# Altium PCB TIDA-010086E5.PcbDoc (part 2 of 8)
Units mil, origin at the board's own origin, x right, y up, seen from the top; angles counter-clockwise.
Board outline 6400 x 6200 mil, 6 copper layers (Top Layer, Power, AGND, Signal, PGND, Bottom Layer), stack 70.536 mil thick; 717 components, 376 nets, 2259 pads, 2183 vias.
Unrouted connection lines stored in the file: 1424.
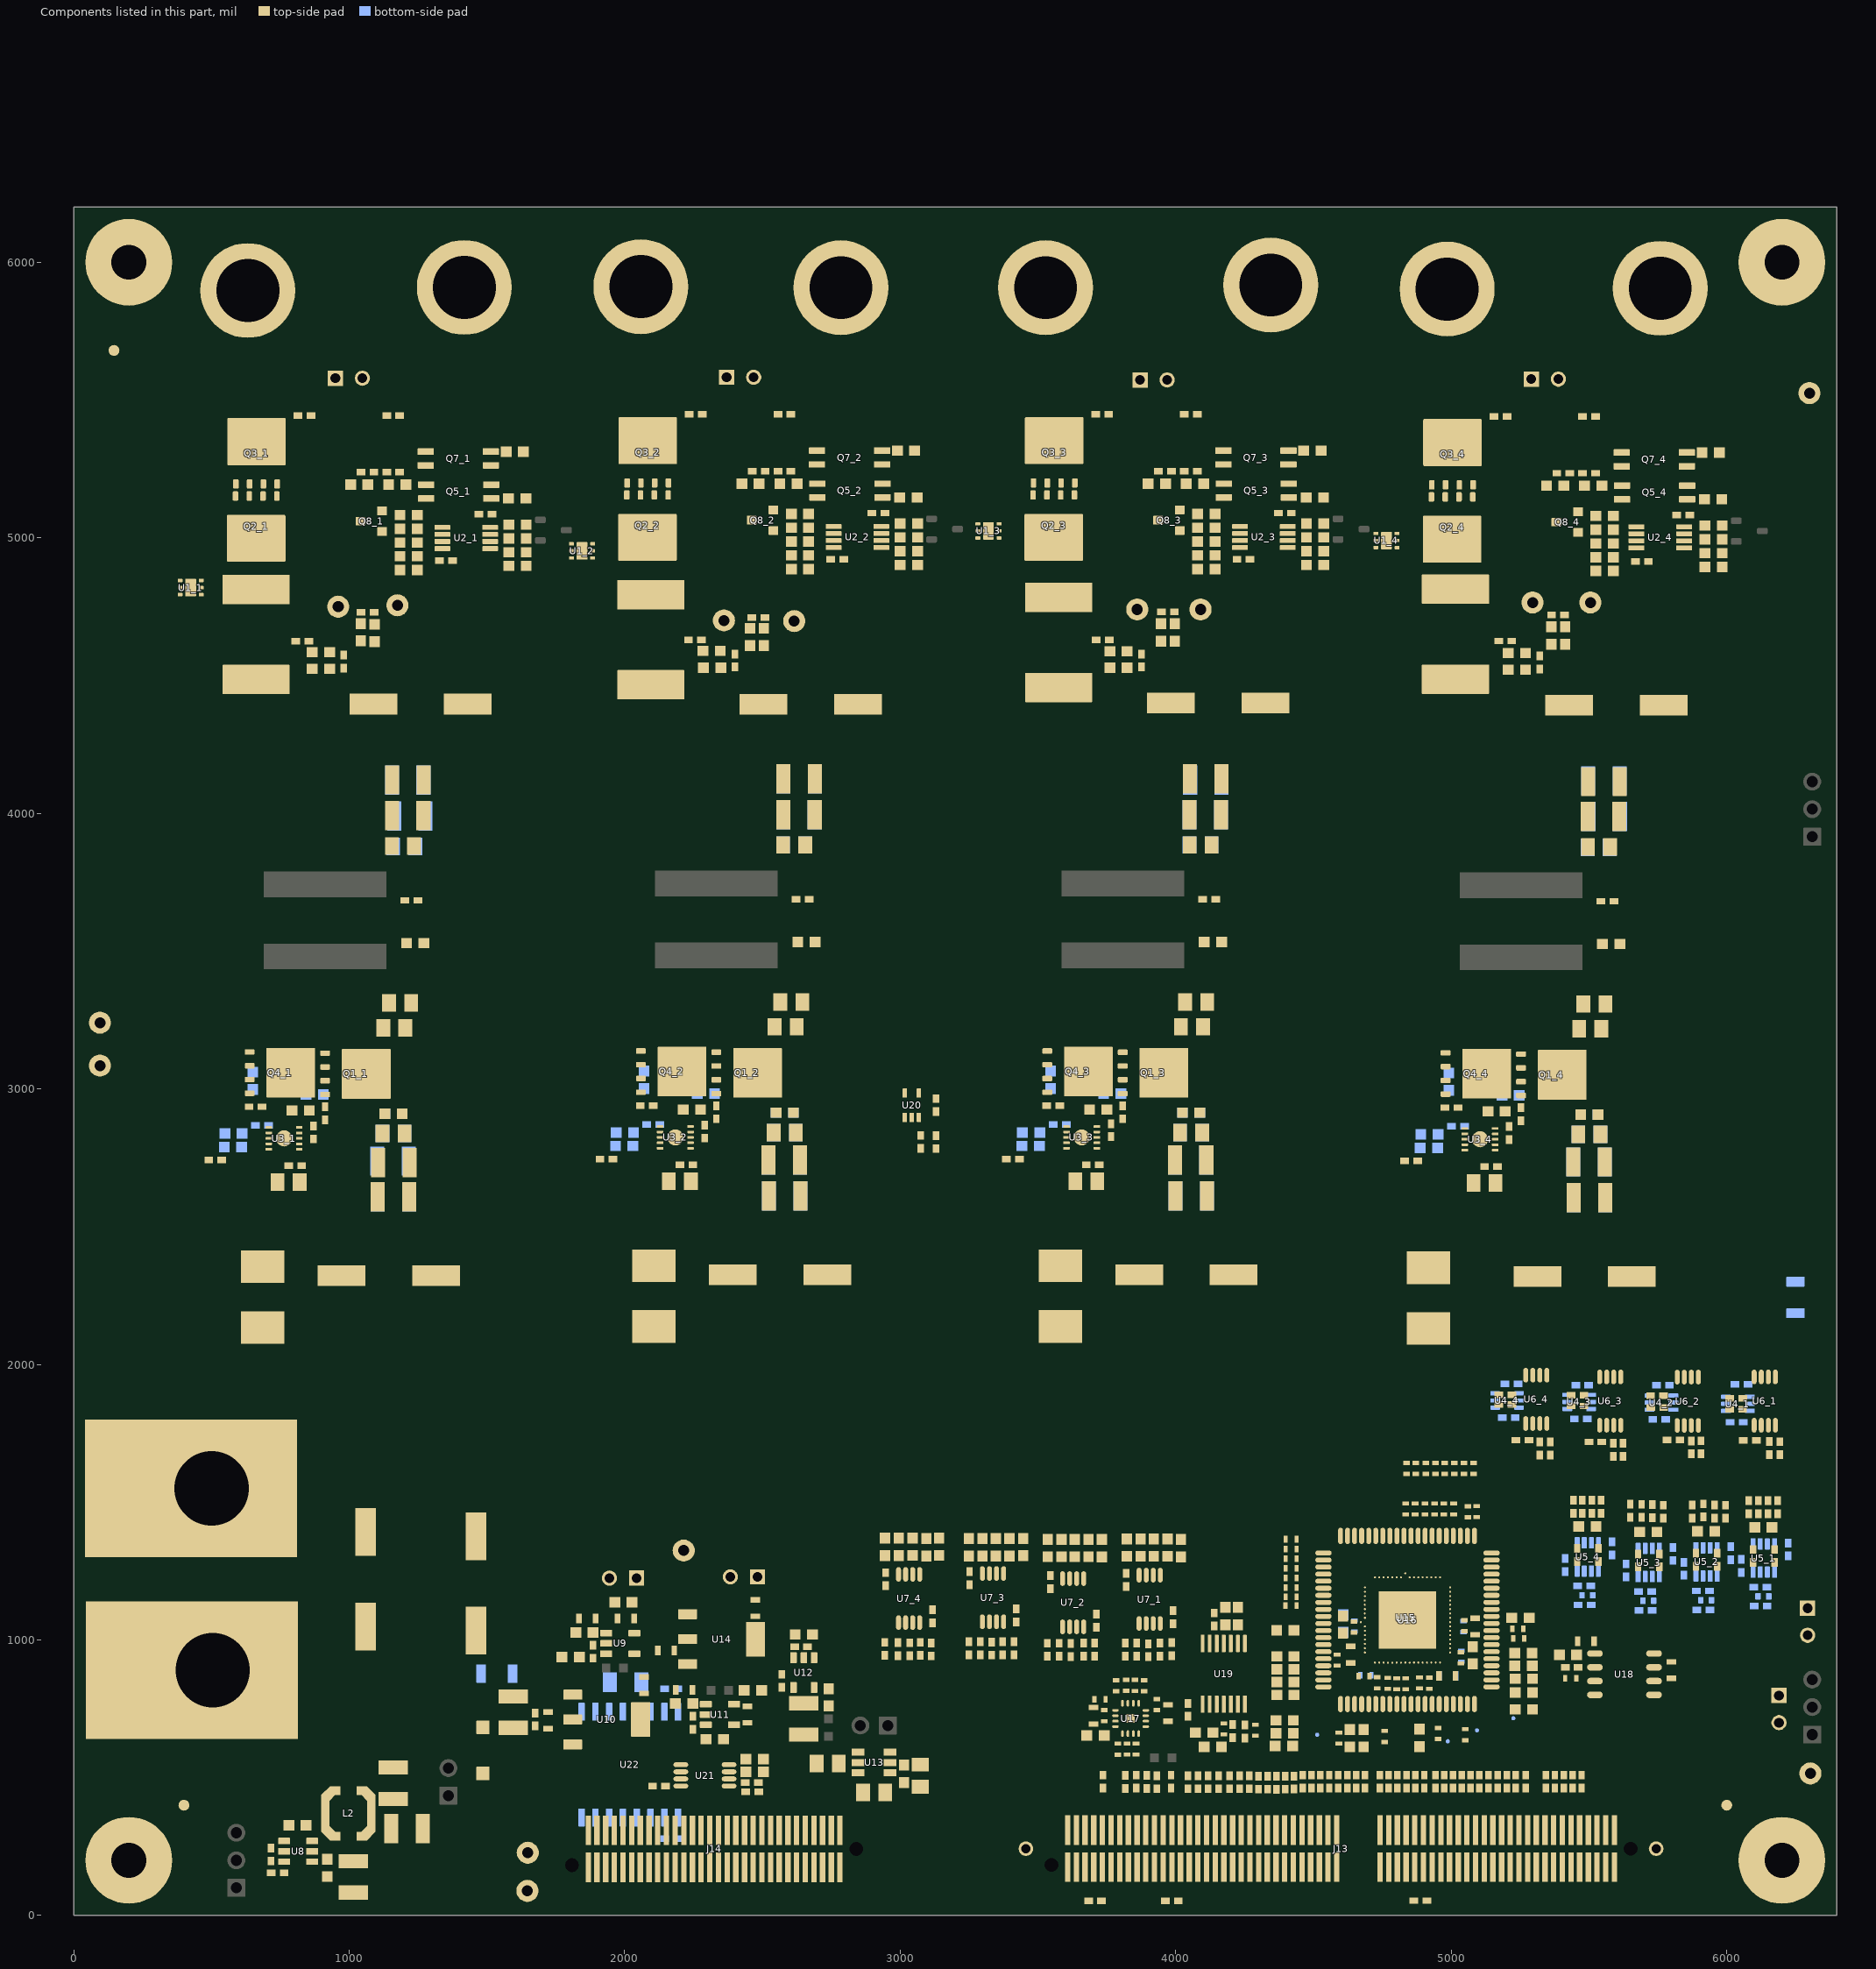
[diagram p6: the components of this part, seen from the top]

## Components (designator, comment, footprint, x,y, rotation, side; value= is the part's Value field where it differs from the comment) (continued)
R27_1 "CRCW04020000Z0ED" 0402 1065.85,5237.76 r0 top value=0 (schematic designator R27)
R27_2 "CRCW04020000Z0ED" 0402 2485.97,5241.34 r0 top value=0 (schematic designator R27)
R27_3 "CRCW04020000Z0ED" 0402 3960.97,5241.34 r0 top value=0 (schematic designator R27)
R27_4 "CRCW04020000Z0ED" 0402 5406.75,5234.5 r0 top value=0 (schematic designator R27)
R28_1 "CRCW060349K9FKEA" 0603 1610.85,4947.76 r0 top value=49.9k (schematic designator R28)
R28_2 "CRCW060349K9FKEA" 0603 3030.97,4951.34 r0 top value=49.9k (schematic designator R28)
R28_3 "CRCW060349K9FKEA" 0603 4505.97,4951.34 r0 top value=49.9k (schematic designator R28)
R28_4 "CRCW060349K9FKEA" 0603 5951.75,4944.5 r0 top value=49.9k (schematic designator R28)
R29_1 "CRCW06031K00JNEA" 0603 1600.85,5312.76 r0 top value=1.0k (schematic designator R29)
R29_2 "CRCW06031K00JNEA" 0603 3020.97,5316.34 r0 top value=1.0k (schematic designator R29)
R29_3 "CRCW06031K00JNEA" 0603 4495.97,5316.34 r0 top value=1.0k (schematic designator R29)
R29_4 "CRCW06031K00JNEA" 0603 5941.75,5309.5 r0 top value=1.0k (schematic designator R29)
R30_1 "CRCW06034K99FKEAC" 0603 1610.85,4997.76 r180 top value=4.99k (schematic designator R30)
R30_2 "CRCW06034K99FKEAC" 0603 3030.97,5001.34 r180 top value=4.99k (schematic designator R30)
R30_3 "CRCW06034K99FKEAC" 0603 4505.97,5001.34 r180 top value=4.99k (schematic designator R30)
R30_4 "CRCW06034K99FKEAC" 0603 5951.75,4994.5 r180 top value=4.99k (schematic designator R30)
R31_1 "CRCW04020000Z0ED" 0402 1159.52,5237.76 r0 top value=0 (schematic designator R31)
R31_2 "CRCW04020000Z0ED" 0402 2579.64,5241.34 r0 top value=0 (schematic designator R31)
R31_3 "CRCW04020000Z0ED" 0402 4054.64,5241.34 r0 top value=0 (schematic designator R31)
R31_4 "CRCW04020000Z0ED" 0402 5500.42,5234.5 r0 top value=0 (schematic designator R31)
R32_1 "CRCW04020000Z0ED" 0402 6033.68,1837.57 r180 top value=0 (schematic designator R32)
R32_2 "CRCW04020000Z0ED" 0402 5747.37,1842.75 r180 top value=0 (schematic designator R32)
R32_3 "CRCW04020000Z0ED" 0402 5458.04,1848.89 r180 top value=0 (schematic designator R32)
R32_4 "CRCW04020000Z0ED" 0402 5196.24,1853.83 r180 top value=0 (schematic designator R32)
R33_1 "CRCW04020000Z0ED" 0402 6172.82,1304.5 r270 top value=0 (schematic designator R33)
R33_2 "CRCW04020000Z0ED" 0402 5964.79,1290.69 r270 top value=0 (schematic designator R33)
R33_3 "CRCW04020000Z0ED" 0402 5754.87,1288.41 r270 top value=0 (schematic designator R33)
R33_4 "CRCW04020000Z0ED" 0402 5533.78,1308.4 r270 top value=0 (schematic designator R33)
R34_1 "CRCW0402499RFKED" 0402 6149.41,1481.6 r270 top value=499 (schematic designator R34)
R34_2 "CRCW0402499RFKED" 0402 5955.6,1465.3 r270 top value=499 (schematic designator R34)
R34_3 "CRCW0402499RFKED" 0402 5729.35,1467.44 r270 top value=499 (schematic designator R34)
R34_4 "CRCW0402499RFKED" 0402 5510.48,1483.4 r270 top value=499 (schematic designator R34)
R35_1 "CRCW04020000Z0ED" 0402 6053.15,1927.64 r0 bottom value=0 (schematic designator R35)
R35_2 "CRCW04020000Z0ED" 0402 5768.23,1923.89 r0 bottom value=0 (schematic designator R35)
R35_3 "CRCW04020000Z0ED" 0402 5475.29,1925.07 r0 bottom value=0 (schematic designator R35)
R35_4 "CRCW04020000Z0ED" 0402 5218.14,1929.83 r0 bottom value=0 (schematic designator R35)
R36_1 "RT0402BRD0720KL" 0402 6121.63,1191.75 r180 bottom value=20.0k (schematic designator R36)
R36_2 "RT0402BRD0720KL" 0402 5913.61,1177.94 r180 bottom value=20.0k (schematic designator R36)
R36_3 "RT0402BRD0720KL" 0402 5703.69,1175.65 r180 bottom value=20.0k (schematic designator R36)
R36_4 "RT0402BRD0720KL" 0402 5482.6,1195.65 r180 bottom value=20.0k (schematic designator R36)
R37_1 "CRCW0402499RFKED" 0402 6114.41,1481.6 r270 top value=499 (schematic designator R37)
R37_2 "CRCW0402499RFKED" 0402 5915,1470 r270 top value=499 (schematic designator R37)
R37_3 "CRCW0402499RFKED" 0402 5690.85,1468.43 r270 top value=499 (schematic designator R37)
R37_4 "CRCW0402499RFKED" 0402 5475.48,1483.4 r270 top value=499 (schematic designator R37)
R38_1 "RT0402BRD07100RL" FP-RT0402BRD07100RL_0402-MFG 6132.82,1158.12 r180 bottom value=100 (schematic designator R38)
R38_2 "RT0402BRD07100RL" FP-RT0402BRD07100RL_0402-MFG 5924.79,1144.32 r180 bottom value=100 (schematic designator R38)
R38_3 "RT0402BRD07100RL" FP-RT0402BRD07100RL_0402-MFG 5714.87,1142.03 r180 bottom value=100 (schematic designator R38)
R38_4 "RT0402BRD07100RL" FP-RT0402BRD07100RL_0402-MFG 5493.78,1162.02 r180 bottom value=100 (schematic designator R38)
R39_1 "CRCW04020000Z0ED" 0402 6033.95,1876.79 r180 top value=0 (schematic designator R39)
R39_2 "CRCW04020000Z0ED" 0402 5747.04,1885.9 r180 top value=0 (schematic designator R39)
R39_3 "CRCW04020000Z0ED" 0402 5458.04,1888.42 r180 top value=0 (schematic designator R39)
R39_4 "CRCW04020000Z0ED" 0402 5196.24,1888.83 r180 top value=0 (schematic designator R39)
R40_1 "CRCW04020000Z0ED" 0402 6122.82,1123.12 r180 bottom value=0 (schematic designator R40)
R40_2 "CRCW04020000Z0ED" 0402 5914.79,1109.32 r180 bottom value=0 (schematic designator R40)
R40_3 "CRCW04020000Z0ED" 0402 5704.87,1107.03 r180 bottom value=0 (schematic designator R40)
R40_4 "CRCW04020000Z0ED" 0402 5483.78,1127.02 r180 bottom value=0 (schematic designator R40)
R41_1 "CRCW04020000Z0ED" 0402 6096.04,1304.5 r270 top value=0 (schematic designator R41)
R41_2 "CRCW04020000Z0ED" 0402 5888.02,1290.69 r270 top value=0 (schematic designator R41)
R41_3 "CRCW04020000Z0ED" 0402 5678.1,1288.41 r270 top value=0 (schematic designator R41)
R41_4 "CRCW04020000Z0ED" 0402 5457.01,1308.4 r270 top value=0 (schematic designator R41)
R42_1 "CRCW060310K0FKEA" 0603 1239.52,3529.08 r180 top value=10.0k (schematic designator R42)
R42_2 "CRCW060310K0FKEA" 0603 2659.64,3532.67 r180 top value=10.0k (schematic designator R42)
R42_3 "CRCW060310K0FKEA" 0603 4134.64,3532.67 r180 top value=10.0k (schematic designator R42)
R42_4 "CRCW060310K0FKEA" 0603 5580.42,3525.83 r180 top value=10.0k (schematic designator R42)
R43 "CRCW04020000Z0ED" 0402S 5080.95,1622.46 r270 top value=0
R44_1 "PCF0402-12-10K0BT1" 0402 3985.69,966.05 r270 top value=10.0k (schematic designator R44)
R44_2 "PCF0402-12-10K0BT1" 0402 3705,965 r270 top value=10.0k (schematic designator R44)
R44_3 "PCF0402-12-10K0BT1" 0402 3412.54,969.36 r270 top value=10.0k (schematic designator R44)
R44_4 "PCF0402-12-10K0BT1" 0402 3112.68,965.47 r270 top value=10.0k (schematic designator R44)
R45_1 "CRCW060320K0FKEA" 0603 4018.88,1332.82 r270 top value=20.0k (schematic designator R45)
R45_2 "CRCW060320K0FKEA" 0603 3731.74,1332.8 r270 top value=20.0k (schematic designator R45)
R45_3 "CRCW060320K0FKEA" 0603 3446.51,1336.9 r270 top value=20.0k (schematic designator R45)
R45_4 "CRCW060320K0FKEA" 0603 3141.03,1338.15 r270 top value=20.0k (schematic designator R45)
R46_1 "CRCW040240K2FKED" 0402 3942.54,964.91 r90 top value=40.2k (schematic designator R46)
R46_2 "CRCW040240K2FKED" 0402 3665.85,965 r90 top value=40.2k (schematic designator R46)
R46_3 "CRCW040240K2FKED" 0402 3371.54,969.36 r90 top value=40.2k (schematic designator R46)
R46_4 "CRCW040240K2FKED" 0402 3072.4,967.26 r90 top value=40.2k (schematic designator R46)
R47_1 "CRCW060349K9FKEA" 0603 3970.3,1335.12 r90 top value=49.9k (schematic designator R47)
R47_2 "CRCW060349K9FKEA" 0603 3682.95,1333.57 r90 top value=49.9k (schematic designator R47)
R47_3 "CRCW060349K9FKEA" 0603 3396.51,1336.34 r90 top value=49.9k (schematic designator R47)
R47_4 "CRCW060349K9FKEA" 0603 3094.57,1336.34 r90 top value=49.9k (schematic designator R47)
R48_1 "CRCW040240K2FKED" 0402 3900.3,962.37 r90 top value=40.2k (schematic designator R48)
R48_2 "CRCW040240K2FKED" 0402 3618.88,962.92 r90 top value=40.2k (schematic designator R48)
R48_3 "CRCW040240K2FKED" 0402 3331.51,968.58 r90 top value=40.2k (schematic designator R48)
R48_4 "CRCW040240K2FKED" 0402 3034.36,965.68 r90 top value=40.2k (schematic designator R48)
R49_1 "CRCW04020000Z0ED" 0402 6154.37,1696.52 r270 top value=0 (schematic designator R49)
R49_2 "CRCW04020000Z0ED" 0402 5871.37,1698.64 r270 top value=0 (schematic designator R49)
R49_3 "CRCW04020000Z0ED" 0402 5587.6,1690.07 r270 top value=0 (schematic designator R49)
R49_4 "CRCW04020000Z0ED" 0402 5321.48,1694.89 r270 top value=0 (schematic designator R49)
R50_1 "CRCW060349K9FKEA" 0603 3920.3,1335.12 r90 top value=49.9k (schematic designator R50)
R50_2 "CRCW060349K9FKEA" 0603 3632.95,1333.57 r90 top value=49.9k (schematic designator R50)
R50_3 "CRCW060349K9FKEA" 0603 3346.51,1336.34 r90 top value=49.9k (schematic designator R50)
R50_4 "CRCW060349K9FKEA" 0603 3044.99,1338.15 r90 top value=49.9k (schematic designator R50)
R51_1 "PCF0402-12-10K0BT1" 0402 3816.32,964.64 r270 top value=10.0k (schematic designator R51)
R51_2 "PCF0402-12-10K0BT1" 0402 3533.43,964.2 r270 top value=10.0k (schematic designator R51)
R51_3 "PCF0402-12-10K0BT1" 0402 3248.72,969.4 r270 top value=10.0k (schematic designator R51)
R51_4 "PCF0402-12-10K0BT1" 0402 2943.3,967.46 r270 top value=10.0k (schematic designator R51)
R52_1 "CRCW060320K0FKEA" 0603 3872.5,1335.12 r270 top value=20.0k (schematic designator R52)
R52_2 "CRCW060320K0FKEA" 0603 3585.15,1333.57 r270 top value=20.0k (schematic designator R52)
R52_3 "CRCW060320K0FKEA" 0603 3298.72,1336.34 r270 top value=20.0k (schematic designator R52)
R52_4 "CRCW060320K0FKEA" 0603 2994.39,1337.58 r270 top value=20.0k (schematic designator R52)
R53 "CRCW0402255KFKED" 0402 740,155 r0 top value=255k
R54 "CRCW040222K1FKED" 0402 715.84,221.1 r270 top value=22.1k
R55 "CRCW12060000Z0EAC" FP-CRCW12060000Z0EAC_1206-MFG 6249.33,2242.79 r90 bottom value=0
R56 "CRCW12060000Z0EAC" FP-CRCW12060000Z0EAC_1206-MFG 1536.07,877.68 r0 bottom value=0
R57 "CRCW06031K00JNEA" 0603 1995.31,1136.75 r0 top value=1.0k
R58 "CRCW06031K00JNEA" 0603 2465.39,817.01 r0 top value=1.0k
R59 "CRCW060349K9FKEA" 0603 1853.82,1027.18 r180 top value=49.9k
R60 "CRCW060349K9FKEA" 0603 2215.39,769.22 r180 top value=49.9k
R61 "CRCW060310K0FKEA" 0603 1803.82,937.37 r0 top value=10.0k
R62 "CRCW060310K0FKEA" 0603 2326.89,639.22 r180 top value=10.0k
R63 "CRCW06031K00JNEA" 0603 3013.77,513.77 r90 top value=1.0k
R64 "CRCW06031K00JNEA" 0603 2740,791.42 r90 top value=1.0k
R65 "CRCW04020000Z0ED" 0402S 4801.97,840.58 r270 top value=0
R66 "CRCW04020000Z0ED" 0402S 4768.67,842.04 r270 top value=0
R67 "CRCW04020000Z0ED" 0402S 4884.57,843.8 r270 top value=0
R68 "CRCW04020000Z0ED" 0402S 4730.96,844.49 r270 top value=0
R69 "CRCW060310K0FKEA" 0603 4392.66,614.55 r0 top value=10.0k
R70 "CRCW060310K0FKEA" 0603 5263.2,808.55 r0 top value=10.0k
R71 "CRCW04020000Z0ED" 0402S 4591.96,643.38 r270 top value=0
R72 "CRCW04020000Z0ED" 0402S 5092.75,1466 r270 top value=0
R73 "CRCW04020000Z0ED" 0402S 4919.78,842.68 r270 top value=0
R74 "CRCW04020000Z0ED" 0402S 5245,1005 r180 top value=0
R75 "CRCW04020000Z0ED" 0402S 4758.37,649.4 r270 top value=0
R76 "CRCW04020000Z0ED" 0402S 5241.76,1040.85 r180 top value=0
R77 "CRCW04020000Z0ED" 0402S 4951.84,660.34 r270 top value=0
R78 "CRCW04020000Z0ED" 0402S 4585.69,926.36 r270 top value=0
R79 "CRCW04020000Z0ED" 0402S 5051.1,655.86 r270 top value=0
R80 "CRCW060310K0FKEA" 0603 5263.2,748.07 r180 top value=10.0k
R81 "CRCW060310K0FKEA" 0603 4397.92,893.58 r0 top value=10.0k
R82 "CRCW060310K0FKEA" 0603 4395.14,661.05 r0 top value=10.0k
R83 "CRCW060310K0FKEA" 0603 4395.14,708.14 r0 top value=10.0k
R84 "CRCW060310K0FKEA" 0603 5263.2,859.01 r180 top value=10.0k
R85 "CRCW060310K0FKEA" 0603 5262.01,906.01 r180 top value=10.0k
R86 "CRCW060310K0FKEA" 0603 5261.89,952.01 r180 top value=10.0k
R87 "CRCW04020000Z0ED" 0402S 4418.38,1330.45 r0 top value=0
R88 "CRCW04020000Z0ED" 0402S 4418.38,1365.45 r0 top value=0
R89 "CRCW04020000Z0ED" 0402S 4418.38,1260.45 r0 top value=0
R90 "CRCW060310K0FKEA" 0603 4397.92,800.57 r0 top value=10.0k
R91 "CRCW060310K0FKEA" 0603 4681.96,643.38 r270 top value=10.0k
R92 "CRCW060310K0FKEA" 0603 4631.96,643.38 r90 top value=10.0k
R93 "CRCW060310K0FKEA" 0603 4397.92,847.14 r180 top value=10.0k
R94 "CRCW04020000Z0ED" 0402S 4418.38,1295.45 r0 top value=0
R95 "CRCW04020000Z0ED" 0402S 4418.38,1190.45 r0 top value=0
R96 "CRCW04020000Z0ED" 0402S 4418.38,1225.45 r0 top value=0
R97 "CRCW04020000Z0ED" 0402S 4418.35,1124.62 r0 top value=0
R98 "CRCW060310K0FKEA" 0603 4397.92,940.15 r180 top value=10.0k
R99 "CRCW04020000Z0ED" 0402S 4418.38,1156.78 r0 top value=0
R100 "CRCW04020000Z0ED" 0402S 3852.41,834.83 r270 top value=0
R101 "CRCW04020000Z0ED" 0402S 3820,835 r270 top value=0
R102 "CRCW04020000Z0ED" 0402S 3783.87,833.66 r270 top value=0
R103 "CRCW04020000Z0ED" 0402S 3725,785 r0 top value=0
R104 "CRCW04020000Z0ED" 0402S 3885.06,833.66 r90 top value=0
R105 "CRCW04020000Z0ED" 0402S 3823.61,603.97 r270 top value=0
R106 "CRCW04020000Z0ED" 0402S 3790.35,603.38 r270 top value=0
R107 "CRCW04020000Z0ED" 0402S 3855.8,604.14 r270 top value=0
R108 "CRCW060310K0FKEA" 0603 3708.5,653.22 r180 top value=10.0k
R109 "CRCW04020000Z0ED" 0402S 5433.64,860.5 r180 top value=0
R110 "CRCW060310K0FKEA" 0603 4102.74,663.27 r0 top value=10.0k
R111 "CRCW0402499RFKED" 0402 4043.58,746.13 r90 top value=499
R112 "ERJ-2BQFR22X" 0402 5437.26,900.5 r0 top value=0.22
R113 "CRCW060315K8FKEA" 0603 4134.23,611.84 r180 top value=15.8k
R114 "CRCW060310K0FKEA" 0603 4180,1086.5 r90 top value=10.0k
R115 "CRCW0402499RFKED" 0402 4251,667.27 r270 top value=499
R116 "CRCW060310K0FKEA" 0603 4225.41,1086.5 r90 top value=10.0k
R117 "CRCW04020000Z0ED" 0402S 4288.86,672.16 r270 top value=0
R118 "CRCW0402100RFKED" 0402 5234.07,485.5 r270 top value=100
R119 "CRCW0402100RFKED" 0402 5169.07,485.5 r270 top value=100
R120 "CRCW0402100RFKED" 0402 5102.07,485.5 r270 top value=100
R121 "CRCW0402100RFKED" 0402 5006.07,485.5 r270 top value=100
R122 "ERA-2AEB102X" 0402 3073.99,2807.11 r90 top value=1.00k
R123 "CRCW04020000Z0ED" 0402 5473,485.5 r270 top value=0
R124 "CRCW04020000Z0ED" 0402 5408.07,485.5 r90 top value=0
R125 "ERA-2AEB102X" 0402 3983,485.5 r270 top value=1.00k
R126 "CRCW04020000Z0ED" 0402 5376.07,485.5 r90 top value=0
R127 "CRCW04020000Z0ED" 0402 5343.07,485.5 r90 top value=0
R128 "CRCW04020000Z0ED" 0402 5270.07,485.5 r90 top value=0
R129 "CRCW04020000Z0ED" 0402 4974.07,485.5 r90 top value=0
R130 "CRCW040222R0JNED" 0402 4838,485.5 r270 top value=22
R131 "CRCW04020000Z0ED" 0402 4942.07,485.5 r90 top value=0
R132 "CRCW040222R0JNED" 0402 4804.07,485.5 r270 top value=22
R133 "CRCW04020000Z0ED" 0402 4902,485.5 r90 top value=0
R134 "CRCW040222R0JNED" 0402 4772.07,485.5 r270 top value=22
R135 "CRCW040222R0JNED" 0402 4870,485.5 r90 top value=22
R136 "CRCW040222R0JNED" 0402 4740.07,485.5 r270 top value=22
R137 "CRCW040222R0JNED" 0402 4687,485.5 r90 top value=22
R138 "CRCW04020000Z0ED" 0402 4590,485.5 r90 top value=0
R139 "CRCW04020000Z0ED" 0402 4557,485.5 r90 top value=0
R140 "CRCW040222R0JNED" 0402 4525,485.5 r90 top value=22
R141 "CRCW040222R0JNED" 0402 4429.15,482.17 r270 top value=22
R142 "CRCW040222R0JNED" 0402 4623,485.5 r90 top value=22
R143 "CRCW0402100RFKED" 0402 2462.5,449.18 r0 top value=100
R144 "CRCW040222R0JNED" 0402 4397,481.88 r270 top value=22
R145 "CRCW040222R0JNED" 0402 4493,485.5 r90 top value=22
R146 "CRCW040222R0JNED" 0402 4365,481.25 r270 top value=22
R147 "CRCW040222R0JNED" 0402 4461,485.5 r90 top value=22
R148 "CRCW040222R0JNED" 0402 4333.3,481.88 r270 top value=22
R149 "CRCW040222R0JNED" 0402 4655,485.5 r90 top value=22
R150 "CRCW040222R0JNED" 0402 4299.66,481.88 r270 top value=22
R151 "CRCW040222R0JNED" 0402 4267.2,483.38 r270 top value=22
R152 "CRCW040222R0JNED" 0402 4232.3,483.38 r270 top value=22
R153 "CRCW040222R0JNED" 0402 4043.58,483.38 r90 top value=22
R154 "CRCW040222R0JNED" 0402 4194.93,483.38 r270 top value=22
R155 "CRCW040222R0JNED" 0402 4155.93,483.38 r90 top value=22
R156 "CRCW06034K99FKEAC" 0603 2471.5,567.18 r180 top value=4.99k
R157 "CRCW060349K9FKEA" 0603 2471.5,521.18 r0 top value=49.9k
R158 "CRCW040222R0JNED" 0402 4117.05,483.38 r270 top value=22
R159 "CRCW040222R0JNED" 0402 4081.27,483.38 r270 top value=22
R160 "CRCW040222R0JNED" 0402 3931.43,483.38 r270 top value=22
R161 "CRCW040222R0JNED" 0402 3895,484.3 r270 top value=22
R162 "CRCW040222R0JNED" 0402 3857,485.5 r270 top value=22
R163 "CRCW040222R0JNED" 0402 3816.27,484.3 r270 top value=22
R164 "ERJ-8ENF59R0V" 1206 2003.59,846.27 r0 bottom value=59.0
R165 "CRCW04020000Z0ED" 0402S 5045.53,1622.46 r270 top value=0
R166 "CRCW04020000Z0ED" 0402S 5060,1465 r270 top value=0
R167 "CRCW04020000Z0ED" 0402S 5011.6,1622.46 r270 top value=0
R168 "CRCW04020000Z0ED" 0402S 5008.7,1475 r270 top value=0
R169 "CRCW04020000Z0ED" 0402S 4975.53,1622.46 r270 top value=0
R170 "CRCW04020000Z0ED" 0402S 4972.63,1475 r270 top value=0
R171 "CRCW04020000Z0ED" 0402S 4942.37,1622.46 r270 top value=0
R172 "CRCW04020000Z0ED" 0402S 4939.47,1475 r270 top value=0
R173 "CRCW04020000Z0ED" 0402S 4907.37,1622.46 r270 top value=0
R174 "CRCW04020000Z0ED" 0402S 4904.47,1475 r270 top value=0
R175 "CRCW04020000Z0ED" 0402S 4871.56,1622.46 r270 top value=0
R176 "CRCW04020000Z0ED" 0402S 4868.66,1475 r270 top value=0
R177 "CRCW04020000Z0ED" 0402S 4837.02,1622.46 r270 top value=0
R178 "CRCW04020000Z0ED" 0402S 4834.12,1475 r270 top value=0
R179 "CRCW04020000Z0ED" 0402S 4834.68,840.58 r270 top value=0
SH-J1 "60900213421" Wurth_60900213421 1187.27,648.32 r180 top
SH-J2 "60900213421" Wurth_60900213421 590,251.54 r270 top
SH-J3 "60900213421" Wurth_60900213421 2895.52,675.23 r0 top
T1 "CXS70-14-C" Panduit_CXS70-14-C 500.19,1550 r0 top
T2 "CXS70-14-C" Panduit_CXS70-14-C 504.28,890 r0 top
TP1_1 "5000" Keystone5000 1175,4755 r90 top (schematic designator TP1)
TP1_2 "5000" Keystone5000 2614.97,4697.68 r90 top (schematic designator TP1)
TP1_3 "5000" Keystone5000 4090,4740 r90 top (schematic designator TP1)
TP1_4 "5000" Keystone5000 5505,4765 r90 top (schematic designator TP1)
TP2_1 "5001" Keystone5001 960,4750 r90 top (schematic designator TP2)
TP2_2 "5001" Keystone5001 2360,4700 r90 top (schematic designator TP2)
TP2_3 "5001" Keystone5001 3860,4740 r90 top (schematic designator TP2)
TP2_4 "5001" Keystone5001 5295,4765 r90 top (schematic designator TP2)
TP3 "5001" Keystone5001 95.14,3240 r180 top
TP4 "5001" Keystone5001 6300,5525 r180 top
TP5 "5001" Keystone5001 95.14,3084.28 r180 top
TP6 "5001" Keystone5001 2213.97,1324.52 r180 top
TP7 "TP_SM_1MM" TP_SM_1MM 5093.44,671.82 r90 bottom
TP8 "TP_SM_1MM" TP_SM_1MM 4513.2,655.86 r90 bottom
TP9 "TP_SM_1MM" TP_SM_1MM 4987.31,632.19 r90 bottom
TP10 "TP_SM_1MM" TP_SM_1MM 5225.43,715.5 r90 bottom
TP11 "5001" Keystone5001 6303.42,515.46 r180 top
TP12 "5001" Keystone5001 1647.95,227.63 r270 top
TP13 "5001" Keystone5001 1646.57,89.2 r180 top
U1_1 "TVS0500DRVR" DRV0006A 424.52,4819.36 r0 top (schematic designator U1)
U1_2 "TVS0500DRVR" DRV0006A 1845,4952.72 r0 top (schematic designator U1)
U1_3 "TVS0500DRVR" DRV0006A 3320,5025 r0 top (schematic designator U1)
U1_4 "TVS0500DRVR" DRV0006A 4765,4990 r0 top (schematic designator U1)
U2_1 "LM393BIDGKR" DGK0008A-MFG 1424.64,4999.25 r0 top (schematic designator U2)
U2_2 "LM393BIDGKR" DGK0008A-MFG 2844.76,5002.83 r0 top (schematic designator U2)
U2_3 "LM393BIDGKR" DGK0008A-MFG 4319.76,5002.83 r0 top (schematic designator U2)
U2_4 "LM393BIDGKR" DGK0008A-MFG 5758.65,5001.88 r0 top (schematic designator U2)
U3_1 "UCC27284DRCR" DRC0010J-MFG 763.43,2820.24 r180 top (schematic designator U3)
U3_2 "UCC27284DRCR" DRC0010J-MFG 2183.54,2823.82 r180 top (schematic designator U3)
U3_3 "UCC27284DRCR" DRC0010J-MFG 3658.54,2823.82 r180 top (schematic designator U3)
U3_4 "UCC27284DRCR" DRC0010J-MFG 5104.32,2816.98 r180 top (schematic designator U3)
U4_1 "INA500B" DCK0006A-MFG 6040.31,1856.62 r0 bottom (schematic designator U4)
U4_2 "INA500B" DCK0006A-MFG 5762.95,1861 r0 bottom (schematic designator U4)
U4_3 "INA500B" DCK0006A-MFG 5464.42,1863.89 r0 bottom (schematic designator U4)
U4_4 "INA500B" DCK0006A-MFG 5202.62,1868.83 r0 bottom (schematic designator U4)
U5_1 "INA630" DDF0008A-MFG 6134.43,1296.94 r270 bottom (schematic designator U5)
U5_2 "INA630" DDF0008A-MFG 5926.4,1283.13 r270 bottom (schematic designator U5)
U5_3 "INA630" DDF0008A-MFG 5716.48,1280.85 r270 bottom (schematic designator U5)
U5_4 "INA630" DDF0008A-MFG 5495.4,1300.84 r270 bottom (schematic designator U5)
U6_1 "INA826AIDGK" DGK0008A_N 6137.84,1866.8 r270 top (schematic designator U6)
U6_2 "INA826AIDGK" DGK0008A_N 5858.28,1866.18 r270 top (schematic designator U6)
U6_3 "INA826AIDGK" DGK0008A_N 5576.73,1866.71 r270 top (schematic designator U6)
U6_4 "INA826AIDGK" DGK0008A_N 5308.68,1873.01 r270 top (schematic designator U6)
U7_1 "TLV9152IDGKR" DGK0008A_N 3905.3,1147.29 r90 top (schematic designator U7)
U7_2 "TLV9152IDGKR" DGK0008A_N 3627.46,1134.97 r90 top (schematic designator U7)
U7_3 "TLV9152IDGKR" DGK0008A_N 3336.51,1153.5 r90 top (schematic designator U7)
U7_4 "TLV9152IDGKR" DGK0008A_N 3032.19,1150.31 r90 top (schematic designator U7)
U8 "LMR54410DBVR" DBV0006A-MFG 814.52,232.6 r0 top
U9 "TPS7A2018PDBVR" DBV0005A-MFG 1983.82,987.37 r0 top
U10 "TLV1117LV30DCYR" DCY0004A_N 1934.45,711.08 r0 top
U11 "TPS7A2033PDBVR" DBV0005A-MFG 2345.39,729.22 r0 top
U12 "TPS73633DBVR" DBV0005A_N 2650,881.42 r270 top
U13 "PM-CHP-LM2664M6-6" DBV0006A_M 2905,555 r0 top
U14 "TLV1117LV30DCYR" DCY0004A_N 2351.53,1002.44 r0 top
U15 "ADS9324RSK" RSK0064B-MFG 4841.04,1072.35 r270 top
U16 "ADS8686SIPZA" PZA0080A_N 4841.04,1072.35 r270 top
U17 "DAC60504BRTET" RTE0016D 3836.01,714.88 r270 top
U18 "REF5040AIDR" D0008A_N 5628.64,875.5 r180 top
U19 "LM324BIPWR" PW0014A-MFG 4174.23,876.84 r90 top
U20 "TMP235DCK" DCK0005A_N 3041.86,2940.47 r90 top
U21 "TLV9152IDGKR" DGK0008A_N 2291.1,508.39 r180 top
U22 "ISO1050DWR" DW0016B_HV 2018.51,547.34 r90 bottom
ZZ1 "This Assembly Note is for PCB labels only" AssemblyNoteLabel 0,6600 r0 top
ZZ2 "These assemblies are ESD sensitive, ESD precautions shall be observed." AssemblyNote 0,6500 r0 top
ZZ3 "These assemblies must be clean and free from flux and all contaminants. Use of no clean flux is not acceptable." AssemblyNote 0,6400 r0 top
ZZ4 "These assemblies must comply with workmanship standards IPC-A-610 Class 2, unless otherwise specified." AssemblyNote 0,6300 r0 top

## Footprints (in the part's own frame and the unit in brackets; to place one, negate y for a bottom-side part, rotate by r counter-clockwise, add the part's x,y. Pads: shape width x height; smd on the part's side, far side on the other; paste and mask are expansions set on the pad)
0402 [mm] "0402 from SM-752 data"
  rect 0.8x0.6 smd: 1(-0.6,0) 2(0.6,0)
  silkscreen extent -1.22,-0.52 1.22,0.52, body extent -0.55,-0.3 0.55,0.3, height 0.6
0402S [mil] "Based on C0402S footprint from PADS legacy"
  rect 15x24 smd: 1(-20,0) 2(20,0)
  body extent -22,-12 22,12, height 24
0603 [mm] "0603 from SM-752 data"
  rect 1x0.95 smd: 1(-0.8,0) 2(0.8,0)
  silkscreen extent -1.52,-0.69 1.52,0.69, body extent -0.87,-0.47 0.87,0.47, height 1
0603S [mil]
  rect 20x35 smd: 1(-30,0) 2(30,0)
  body extent -34,-19 34,19, height 39
0805_HV [mil] "0805 with 30mil clearance between pads"
  rect 50x63 smd: 1(-40,0) 2(40,0)
  silkscreen extent -74,-40 74,40, body extent -43,-29 43,29, height 57
1206 [mm] "1206 from SM-752 data"
  rect 1.3x1.85 smd: 1(-1.45,0) 2(1.45,0)
  silkscreen extent -2.4,-1.21 2.4,1.21, body extent -1.7,-0.9 1.7,0.9, height 1.35
1210 [mm] "1210 from SM-752 data"
  rect 1.3x2.7 smd: 1(-1.45,0) 2(1.45,0)
  silkscreen extent -2.32,-1.57 2.32,1.57, body extent -1.7,-1.35 1.7,1.35, height 1.35
1210_270 [mm] "1210"
  rect 1.3x2.7 smd: 1(-1.45,0) 2(1.45,0)
  silkscreen extent -2.32,-1.57 2.32,1.57, body extent -1.7,-1.35 1.7,1.35, height 2.7
1806_HighSpeed [mm] "Wurth recommended land pattern"
  rrect8% 1.25x1.2 smd: 1(-2.125,0) 2(2.125,0)
  silkscreen extent -1.5,-1 1.5,1, body extent -2.25,-0.8 2.25,0.8, height 1.61
6125FA [mm] "Cooper Bussman 6125FA Brick Fuses, recommended land pattern OC-2531 Rev. I 3/07"
  rect 3x4 smd: 1(-2.8,0) 2(2.8,0)
  silkscreen extent -4.57,-2.27 4.57,2.27, body extent -3.17,-1.42 3.17,1.41, height 2.84
AssemblyNote [mil] "Assembly Note"
AssemblyNoteLabel [mil] "Assembly Note for PCB Labels"
CAPSMT_62_F12 [mm] "F12, SMD, 2-Leads, Body 10.5x10.5mm, Height 12.7mm"
  rect 4.4x1.9 smd: 1(-4.35,0) 2(4.35,0)
  silkscreen extent -5.25,-5.25 5.25,5.25, body extent -5.25,-5.25 5.25,5.25, height 12.71
CE_Mark_5mm [mil] "Minimum text height for CE Mark"
  silkscreen extent -138,-98 138,98
controlCARD-120HSEC [mm] "Pads are not numbered according to Samtec datasheet."
  rect 0.5x2.724 smd: 1(-23.357,-1.678) 2(-23.357,1.722) 3(-22.557,-1.678) 4(-22.557,1.722) 5(-21.757,-1.678) 6(-21.757,1.722) 7(-20.957,-1.678) 8(-20.957,1.722) 9(-20.157,-1.678) 10(-20.157,1.722) 11(-19.357,-1.678) 12(-19.357,1.722) 13(-18.557,-1.678) 14(-18.557,1.722) 15(-17.757,-1.678) 16(-17.757,1.722) 17(-16.957,-1.678) 18(-16.957,1.722) 19(-16.157,-1.678) 20(-16.157,1.722) 21(-15.357,-1.678) 22(-15.357,1.722) 23(-14.557,-1.678) 24(-14.557,1.722) 25(-13.757,-1.678) 26(-13.757,1.722) 27(-12.957,-1.678) 28(-12.957,1.722) 29(-12.157,-1.678) 30(-12.157,1.722) 31(-11.357,-1.678) 32(-11.357,1.722) 33(-10.557,-1.678) 34(-10.557,1.722) 35(-9.757,-1.678) 36(-9.757,1.722) 37(-8.957,-1.678) 38(-8.957,1.722) 39(-8.157,-1.678) 40(-8.157,1.722) 41(-7.357,-1.678) 42(-7.357,1.722) 43(-6.557,-1.678) 44(-6.557,1.722) 45(-5.757,-1.678) 46(-5.757,1.722) 47(-4.957,-1.678) 48(-4.957,1.722) 49(-4.157,-1.678) 50(-4.157,1.722) 51(-3.357,-1.678) 52(-3.357,1.722) 53(-2.557,-1.678) 54(-2.557,1.722) 55(-1.757,-1.678) 56(-1.757,1.722) 57(2.243,-1.678) 58(2.243,1.722) 59(3.043,-1.678) 60(3.043,1.722) 61(3.843,-1.678) 62(3.843,1.722) 63(4.643,-1.678) 64(4.643,1.722) 65(5.443,-1.678) 66(5.443,1.722) 67(6.243,-1.678) 68(6.243,1.722) 69(7.043,-1.678) 70(7.043,1.722) 71(7.843,-1.678) 72(7.843,1.722) 73(8.643,-1.678) 74(8.643,1.722) 75(9.443,-1.678) 76(9.443,1.722) 77(10.243,-1.678) 78(10.243,1.722) 79(11.043,-1.678) 80(11.043,1.722) 81(11.843,-1.678) 82(11.843,1.722) 83(12.643,-1.678) 84(12.643,1.722) 85(13.443,-1.678) 86(13.443,1.722) 87(14.243,-1.678) 88(14.243,1.722) 89(15.043,-1.678) 90(15.043,1.722) 91(15.843,-1.678) 92(15.843,1.722) 93(16.643,-1.678) 94(16.643,1.722) 95(17.443,-1.678) 96(17.443,1.722) 97(18.243,-1.678) 98(18.243,1.722) 99(19.043,-1.678) 100(19.043,1.722) 101(19.843,-1.678) 102(19.843,1.722) 103(20.643,-1.678) 104(20.643,1.722) 105(21.443,-1.678) 106(21.443,1.722) 107(22.243,-1.678) 108(22.243,1.722) 109(23.043,-1.678) 110(23.043,1.722) 111(23.843,-1.678) 112(23.843,1.722) 113(24.643,-1.678) 114(24.643,1.722) 115(25.443,-1.678) 116(25.443,1.722) 117(26.243,-1.678) 118(26.243,1.722) 119(27.043,-1.678) 120(27.043,1.722)
  round 0.025 hole 1.27 unplated mask+0.876: 181(-24.857,0.022) 182(28.543,1.522)
  round 1.348 hole 0.84: 185(-27.207,0.022) 186(30.893,0.022)
  silkscreen extent -32.11,-3.86 35.8,3.9, body extent -31.75,-3.48 35.3,3.52, height 12.35
controlCARD-180HSEC-60pinAddon [mm] "Pads are not numbered according to datasheet."
  round 0.025 hole 1.27 unplated mask+0.876: 61(-13.1,0) 62(13.1,1.5)
  rect 0.5x2.724 smd: 121(-11.6,-1.7) 122(-11.6,1.7) 123(-10.8,-1.7) 124(-10.8,1.7) 125(-10,-1.7) 126(-10,1.7) 127(-9.2,-1.7) 128(-9.2,1.7) 129(-8.4,-1.7) 130(-8.4,1.7) 131(-7.6,-1.7) 132(-7.6,1.7) 133(-6.8,-1.7) 134(-6.8,1.7) 135(-6,-1.7) 136(-6,1.7) 137(-5.2,-1.7) 138(-5.2,1.7) 139(-4.4,-1.7) 140(-4.4,1.7) 141(-3.6,-1.7) 142(-3.6,1.7) 143(-2.8,-1.7) 144(-2.8,1.7) 145(-2,-1.7) 146(-2,1.7) 147(-1.2,-1.7) 148(-1.2,1.7) 149(-0.4,-1.7) 150(-0.4,1.7) 151(0.4,-1.7) 152(0.4,1.7) 153(1.2,-1.7) 154(1.2,1.7) 155(2,-1.7) 156(2,1.7) 157(2.8,-1.7) 158(2.8,1.7) 159(3.6,-1.7) 160(3.6,1.7) 161(4.4,-1.7) 162(4.4,1.7) 163(5.2,-1.7) 164(5.2,1.7) 165(6,-1.7) 166(6,1.7) 167(6.8,-1.7) 168(6.8,1.7) 169(7.6,-1.7) 170(7.6,1.7) 171(8.4,-1.7) 172(8.4,1.7) 173(9.2,-1.7) 174(9.2,1.7) 175(10,-1.7) 176(10,1.7) 177(10.8,-1.7) 178(10.8,1.7) 179(11.6,-1.7) 180(11.6,1.7)
  silkscreen extent -14.68,-3.88 14.68,3.88, body extent -14.3,-3.5 14.3,3.5, height 7.95
D0008A_N [mm] "SOIC, 8-Leads, Body 4.9x3.9mm, Pitch 1.27mm, IPC Medium Density"
  oval 1.45x0.6 smd: 1(-2.725,1.905) 2(-2.725,0.635) 3(-2.725,-0.635) 4(-2.725,-1.905) 5(2.725,-1.905) 6(2.725,-0.635) 7(2.725,0.635) 8(2.725,1.905)
  silkscreen extent -3.3,-2.5 0.9,2.5, body extent -3,-2.45 3,2.45, height 1.63
DBV0005A-MFG [mm]
  rrect17% 1.1x0.6 smd paste+0 mask+0: 1(-1.3,0.95) 2(-1.3,0) 3(-1.3,-0.95) 4(1.3,-0.95) 5(1.3,0.95)
  silkscreen extent -2.57,-1.53 0.87,1.53, body extent -1.95,-1.78 1.95,1.78, height 0.25
DBV0005A_N [mm] "SOT23, 5-Leads, Body 2.9x1.6mm, Pitch 0.95mm, Lead Span 2.8mm, IPC Medium Density"
  rrect17% 1x0.6 smd: 1(-1.375,0.95) 2(-1.375,0) 3(-1.375,-0.95) 4(1.375,-0.95) 5(1.375,0.95)
  silkscreen extent -1.63,-1.55 0.38,1.55, body extent -1.42,-1.46 1.42,1.46, height 1.09
DBV0006A-MFG [mm]
  rrect17% 1.1x0.6 smd paste+0 mask+0: 1(-1.3,0.95) 2(-1.3,0) 3(-1.3,-0.95) 4(1.3,-0.95) 5(1.3,0) 6(1.3,0.95)
  silkscreen extent -2.52,-1.53 0.35,1.53, body extent -1.95,-1.78 1.95,1.78, height 0.25
DBV0006A_M [mm] "SOT23, 6-Leads, Body 2.9x1.6mm, Pitch 0.95mm, Lead Span 2.8mm, IPC Low Density"
  rrect15% 1.2x0.65 smd: 1(-1.475,0.95) 2(-1.475,0) 3(-1.475,-0.95) 4(1.475,-0.95) 5(1.475,0) 6(1.475,0.95)
  silkscreen extent -1.83,-1.55 0.38,1.55, body extent -1.42,-1.46 1.42,1.46, height 1.12
DCK0005A_N [mm] "SOT353, 5-Leads, Body 2x1.3mm, Pitch 0.65mm, Lead Span 2.1mm, IPC Medium Density"
  rrect25% 0.85x0.4 smd: 1(-1.125,0.65) 2(-1.125,0) 3(-1.125,-0.65) 4(1.125,-0.65) 5(1.125,0.65)
  silkscreen extent -1.48,-1.02 0.55,1.1, body extent -1.14,-1 1.14,1, height 0.95
DCK0006A-MFG [mm]
  rrect25% 0.9x0.4 smd paste-1000 mask+0: 1(-1.1,0.65) 2(-1.1,0) 3(-1.1,-0.65) 4(1.1,-0.65) 5(1.1,0) 6(1.1,0.65)
  silkscreen extent -2.22,-1.07 0.27,1.07, body extent -1.1,-1 1.1,1, height 1.1
DCY0004A_N [mm] "SOT223/SC73, 4-Leads, Body 6.5x3.5mm, Pitch 2.3mm, Lead Span 7mm, IPC Medium Density"
  rrect11% 1.75x0.9 smd: 1(-3.125,2.3) 2(-3.125,0) 3(-3.125,-2.3)
  rrect6% 1.75x3.2 smd: 4(3.125,0)
  silkscreen extent -3.02,-3.35 1.4,3.47, body extent -3.48,-3.25 3.48,3.25, height 1.68
DDF0008A-MFG [mm]
  rrect22% 1.05x0.45 smd paste+0 mask+0: 1(-1.3,0.975) 2(-1.3,0.325) 3(-1.3,-0.325) 4(-1.3,-0.975) 5(1.3,-0.975) 6(1.3,-0.325) 7(1.3,0.325) 8(1.3,0.975)
  silkscreen extent -2.5,-1.48 0.4,1.48, body extent -1.41,-1.45 1.41,1.45, height 1.1
DFH0004A-MFG [mm]
  rrect17% 1.5x0.6 smd paste+0 mask+0: 1(-3,0.635) 2(-3,-0.635) 3(3,-0.635) 4(3,0.635)
  silkscreen extent -4.43,-1.4 2.45,1.4, body extent -3.85,-1.65 3.85,1.65, height 0.25
DGK0008A-MFG [mm]
  rrect22% 1.45x0.45 smd paste+0 mask+0: 1(-2.2,0.975) 2(-2.2,0.325) 3(-2.2,-0.325) 4(-2.2,-0.975) 5(2.2,-0.975) 6(2.2,-0.325) 7(2.2,0.325) 8(2.2,0.975)
  silkscreen extent -3.62,-1.55 1.1,1.55, body extent -3.03,-1.8 3.03,1.8, height 0.25
DGK0008A_N [mm] "TSOP, 8-Leads, Body 3x3mm, Pitch 0.65mm, IPC Medium Density"
  oval 1.35x0.45 smd: 1(-2.225,0.975) 2(-2.225,0.325) 3(-2.225,-0.325) 4(-2.225,-0.975) 5(2.225,-0.975) 6(2.225,-0.325) 7(2.225,0.325) 8(2.225,0.975)
  silkscreen extent -2.75,-1.55 0.95,1.55, body extent -2.45,-1.5 2.45,1.5, height 0.96
DNK0008A [mm] "SON, 8-Leads, Body 5x6mm"
  rrect39% 0.86x0.51 smd paste-0.05 mask-0.05: 1(-2.82,1.905) 2(-2.82,0.635) 3(-2.82,-0.635) 4(-2.82,-1.905) 5(2.82,-1.905) 6(2.82,-0.635) 7(2.82,0.635) 8(2.82,1.905)
  rrect40% 0.25x0.555 on Top Solder: 9(-0.83,2.372) 9(-0.83,-2.372)
  rrect40% 0.25x0.555 on Top Paste: 9(-0.83,2.372) 9(-0.83,-2.372)
  rrect11% 0.95x1.13 on Top Paste: 9(-0.535,1.33) 9(-0.535,0) 9(-0.535,-1.33) 9(0.615,1.33) 9(0.615,0) 9(0.615,-1.33) 9(1.765,1.33) 9(1.765,0) 9(1.765,-1.33)
  rrect3% 3.58x4 on Top Solder: 9(0.75,0)
  rrect5% 4.34x5.4 smd paste-3 mask-3: 9(1.08,0)
  body extent -3.05,-2.55 3.05,2.55, height 1.06
DQJ0008A [mm] "SMD, 8-Leads, Body 5.75x4.9mm"
  rrect39% 0.91x0.51 smd paste-0.05 mask-0.05: 1(-2.795,1.905) 2(-2.795,0.635) 3(-2.795,-0.635) 4(-2.795,-1.905) 5(2.795,-1.905) 6(2.795,-0.635) 7(2.795,0.635) 8(2.795,1.905)
  rrect8% 1.58x1.25 on Top Paste: 9(-0.38,-1.45) 9(-0.38,0) 9(-0.38,1.45) 9(1.4,-1.45) 9(1.4,0) 9(1.4,1.45)
  rrect3% 3.48x4.47 on Top Solder: 9(0.55,0)
  rrect2% 4.49x4.57 smd paste-2.5 mask-2.5: 9(1.005,0)
  silkscreen extent -3,-2.6 3,2.6, body extent -3.13,-2.45 3.13,2.45, height 1.15
DRC0010J-MFG [mm]
  rrect42% 0.6x0.24 smd paste+0 mask+0: 1(-1.4,1) 2(-1.4,0.5) 3(-1.4,0) 4(-1.4,-0.5) 5(-1.4,-1) 6(1.4,-1) 7(1.4,-0.5) 8(1.4,0) 9(1.4,0.5) 10(1.4,1)
  round 1.485 smd paste-1000 mask+0: 11(0,0)
  Top Layer region: -0.825,-1.15 -0.818,-1.175 -0.8,-1.193 -0.775,-1.2 -0.775,-1.2 -0.375,-1.2 -0.375,-1.65 -0.368,-1.675 -0.35,-1.693 -0.325,-1.7 -0.325,-1.7 -0.175,-1.7 -0.156,-1.696 -0.14,-1.685 -0.129,-1.669 -0.125,-1.65 -0.125,-1.65 -0.125,-1.2 0.125,-1.2 0.125,-1.65 0.129,-1.669 0.14,-1.685 0.156,-1.696 0.175,-1.7 0.175,-1.7 0.325,-1.7 0.35,-1.693 0.368,-1.675 0.375,-1.65 0.375,-1.65 0.375,-1.2 0.775,-1.2 0.8,-1.193 0.818,-1.175 0.825,-1.15 0.825,-1.15 0.825,1.15 0.818,1.175 0.8,1.193 0.775,1.2 0.775,1.2 0.375,1.2 0.375,1.65 0.368,1.675 0.35,1.693 0.325,1.7 0.325,1.7 0.175,1.7 0.156,1.696 0.14,1.685 0.129,1.669 0.125,1.65 0.125,1.65 0.125,1.2 -0.125,1.2 -0.125,1.65 -0.129,1.669 -0.14,1.685 -0.156,1.696 -0.175,1.7 -0.175,1.7 -0.325,1.7 -0.35,1.693 -0.368,1.675 -0.375,1.65 -0.375,1.65 -0.375,1.2 -0.775,1.2 -0.8,1.193 -0.818,1.175 -0.825,1.15 -0.825,1.15
  silkscreen extent -2.5,-1.55 1.55,1.55, body extent -1.8,-1.8 1.8,1.8, height 0.25
DRV0006A [mm] "SON, 6-Leads, Body 2x2mm, Pitch 0.65mm, Thermal Pad 1.6x1mm, TI Recommended"
  rrect33% 0.45x0.3 smd: 1(-0.975,0.65) 2(-0.975,0) 3(-0.975,-0.65) 4(0.975,-0.65) 5(0.975,0) 6(0.975,0.65)
  rrect14% 1x0.7 on Top Paste: 7(0,-0.45) 7(0,0.45)
  rrect10% 1x1.6 smd paste-0.5: 7(0,0)
  silkscreen extent -1.05,-1.2 1.05,1.2, body extent -1.05,-1.05 1.05,1.05, height 0.81
DW0016B_HV [mm] "SOIC-16, HV/isolation option"
  rrect17% 1.65x0.6 smd: 1(-4.875,4.445) 2(-4.875,3.175) 3(-4.875,1.905) 4(-4.875,0.635) 5(-4.875,-0.635) 6(-4.875,-1.905) 7(-4.875,-3.175) 8(-4.875,-4.445) 9(4.875,-4.445) 10(4.875,-3.175) 11(4.875,-1.905) 12(4.875,-0.635) 13(4.875,0.635) 14(4.875,1.905) 15(4.875,3.175) 16(4.875,4.445)
  body extent -5.17,-5.15 5.17,5.15, height 2.59
FCC_disclaimer [mil]
Fiducial10-20 [mm]
  round 1 smd mask+0.5: 1(0,0)
  Top Layer keep-out circle w1.178: c0,0 r0.5
FP-BSS84LT1G_SOT-23-3-318-08-MFG [mm]
  rrect13% 0.9x0.8 smd paste+0 mask+0: 1(-1,0.95) 2(-1,-0.95) 3(1,0)
  silkscreen extent -0.7,-1.52 0.7,1.52, body extent -1.55,-1.62 1.55,1.62, height 0.25
FP-CRCW12060000Z0EAC_1206-MFG [mm]
  rrect11% 0.9x1.7 smd paste+0 mask+0: 1(-1.45,0) 2(1.45,0)
  silkscreen extent -0.63,-0.82 0.63,0.82, body extent -1.53,-0.77 1.53,0.77, height 0.65
FP-CXS35-36T-C_TERMINAL_LUG-MFG [mm]
  round 8.75 hole 5.8 paste-2539.97 mask+0: 1(7.3,0)
  silkscreen extent -13.95,-5.1 13.95,5.1, body extent -14.05,-5.2 14.05,5.2, height 0.25
FP-RT0402BRD07100RL_0402-MFG [mm]
  rrect20% 0.5x0.6 smd paste+0 mask+0: 1(-0.5,0) 2(0.5,0)
  silkscreen extent -0.5,-0.71 0.5,0.7, body extent -0.5,-0.25 0.5,0.25, height 0.35
FP-SEWF3920F2L00P9_3920-MFG [mm]
  rrect4% 2.7x6.2 smd paste+0 mask+0: 1(-4.15,0) 2(4.15,0)
  silkscreen extent -2.42,-2.7 2.42,2.7, body extent -5.6,-3.2 5.6,3.2, height 0.25
IEC_HotSurface_Large [mil]
  silkscreen extent -435,-375 435,378
Johnson_108-0740-001 [mm] "Banana Jack Uninsulated Standard Type"
  round 12 hole 6.858: 1(0,0)
  body extent -4.77,-5.43 4.75,5.57, height 2.39
JST_B2B-EH-A [mm] "Header (Shrouded), 2.5mm, 2x1, TH"
  rect 1.4x1.4 hole 0.9: 1(-1.25,0)
  round 1.4 hole 0.9: 2(1.25,0)
  silkscreen extent -4.2,-2.2 3.75,1.6, body extent -3.75,-2.2 3.75,1.6, height 6
Keystone5000 [mil] "For Keystone 500x miniature loop terminals"
  round 80 hole 40: 1(0,0)
  silkscreen extent -52,-52 52,52, body extent -49,-49 49,49, height 182
Keystone5001 [mil] "For Keystone 500x miniature loop terminals"
  round 80 hole 40: 1(0,0)
  silkscreen extent -52,-52 52,52, body extent -49,-49 49,49, height 182
Keystone_1902C [mil] "Hex Standoff, 4-40 threaded, nylon"
  round 1 on Mech4: 0(0,0)
  body extent -145,-126 146,126, height 501
Label_650x200 [mil] "Thermal Transfer Label"
  round 1 on Mech14: 0(0,0)
  silkscreen extent -325,-100 325,100, body extent -325,-100 325,100, height 1
LPS5015 [mm] "Coilcraft recommended land pattern.  Document 585-2, rev 12/05/08"
  rect 0.75x3.4 smd: 1(-2.125,0) 2(2.125,0)
  rect 1.131x0.92 smd rot 135: 1(-1.776,-1.776) 2(1.776,1.776)
  rect 1.131x0.92 smd rot 45: 1(-1.776,1.776) 2(1.776,-1.776)
  rect 0.95x0.8 smd: 1(-1.225,-2.1) 1(-1.225,2.1) 2(1.225,-2.1) 2(1.225,2.1)
  silkscreen extent -3.45,-2.8 2.8,2.8, body extent -2.5,-2.5 2.51,2.51, height 1.52
"NY PMS 440 0025 PH" [mm] "4-40 nylon screw and mounting hole"
  round 8 hole 3.2: 1(0,0)
  body extent -3.3,-3.3 3.3,3.3, height 2.69
Panduit_CXS70-14-C [mil] "Panduit"
  rect 770x500 hole 270 copper offset -74.8,0 paste-99999: 1(0,0)
  body extent -960,-250 310,250, height 684
PW0014A-MFG [mm]
  rrect29% 1.6x0.35 smd paste-1000 mask+0: 1(-2.8,1.95) 2(-2.8,1.3) 3(-2.8,0.65) 4(-2.8,0) 5(-2.8,-0.65) 6(-2.8,-1.3) 7(-2.8,-1.95) 8(2.8,-1.95) 9(2.8,-1.3) 10(2.8,-0.65) 11(2.8,0) 12(2.8,0.65) 13(2.8,1.3) 14(2.8,1.95)
  silkscreen extent -4.32,-2.55 2.25,2.55, body extent -3.7,-2.8 3.7,2.8, height 0.25
PZA0080A_N [mm] "QFP, 80-Leads, Body 14x14mm, Pitch 0.65mm, IPC Medium Density"
  oval 1.5x0.45 smd: 1(-7.75,6.175) 2(-7.75,5.525) 3(-7.75,4.875) 4(-7.75,4.225) 5(-7.75,3.575) 6(-7.75,2.925) 7(-7.75,2.275) 8(-7.75,1.625) 9(-7.75,0.975) 10(-7.75,0.325) 11(-7.75,-0.325) 12(-7.75,-0.975) 13(-7.75,-1.625) 14(-7.75,-2.275) 15(-7.75,-2.925) 16(-7.75,-3.575) 17(-7.75,-4.225) 18(-7.75,-4.875) 19(-7.75,-5.525) 20(-7.75,-6.175) 41(7.75,-6.175) 42(7.75,-5.525) 43(7.75,-4.875) 44(7.75,-4.225) 45(7.75,-3.575) 46(7.75,-2.925) 47(7.75,-2.275) 48(7.75,-1.625) 49(7.75,-0.975) 50(7.75,-0.325) 51(7.75,0.325) 52(7.75,0.975) 53(7.75,1.625) 54(7.75,2.275) 55(7.75,2.925) 56(7.75,3.575) 57(7.75,4.225) 58(7.75,4.875) 59(7.75,5.525) 60(7.75,6.175)
  oval 0.45x1.5 smd: 21(-6.175,-7.75) 22(-5.525,-7.75) 23(-4.875,-7.75) 24(-4.225,-7.75) 25(-3.575,-7.75) 26(-2.925,-7.75) 27(-2.275,-7.75) 28(-1.625,-7.75) 29(-0.975,-7.75) 30(-0.325,-7.75) 31(0.325,-7.75) 32(0.975,-7.75) 33(1.625,-7.75) 34(2.275,-7.75) 35(2.925,-7.75) 36(3.575,-7.75) 37(4.225,-7.75) 38(4.875,-7.75) 39(5.525,-7.75) 40(6.175,-7.75) 61(6.175,7.75) 62(5.525,7.75) 63(4.875,7.75) 64(4.225,7.75) 65(3.575,7.75) 66(2.925,7.75) 67(2.275,7.75) 68(1.625,7.75) 69(0.975,7.75) 70(0.325,7.75) 71(-0.325,7.75) 72(-0.975,7.75) 73(-1.625,7.75) 74(-2.275,7.75) 75(-2.925,7.75) 76(-3.575,7.75) 77(-4.225,7.75) 78(-4.875,7.75) 79(-5.525,7.75) 80(-6.175,7.75)
  silkscreen extent -7.87,-6.6 6.6,7.08, body extent -7,-7 7,7, height 1.6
